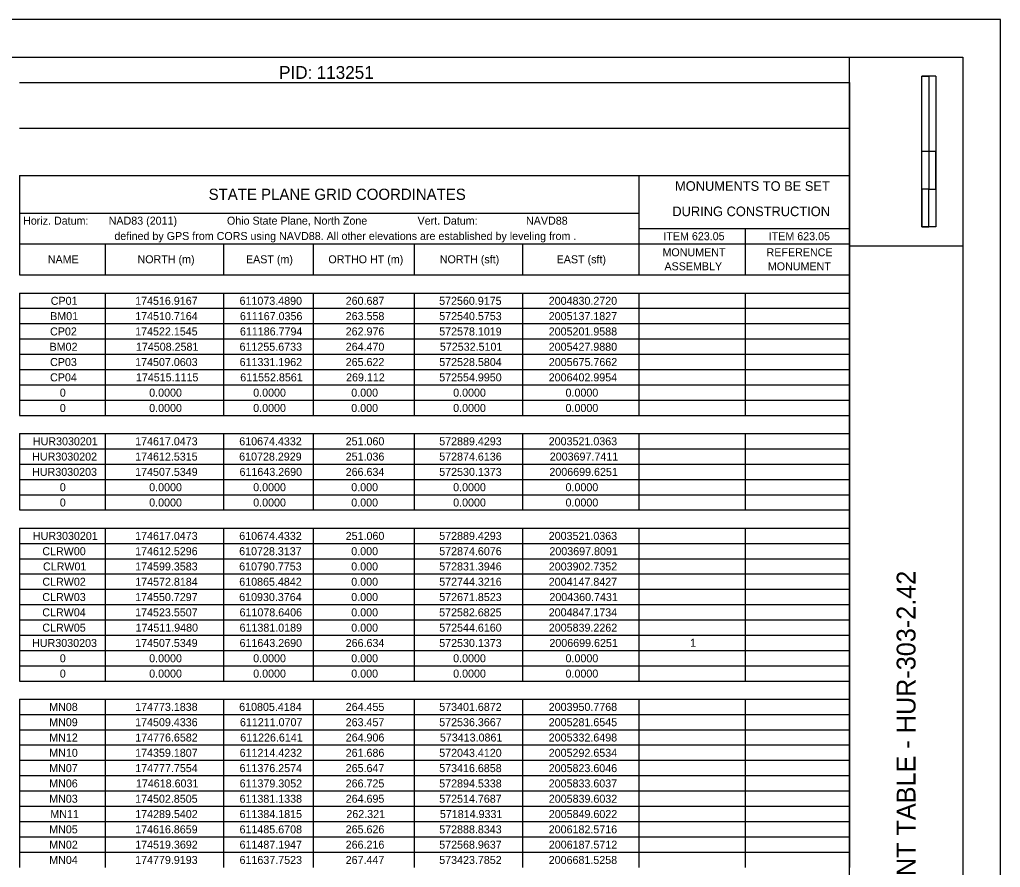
# Model space of a CAD drawing. Extents: x 0 to 34, y 0 to 22.
# Drawn here: x 21 to 34, y 10.76 to 22 of the extents above; entities that cross this region are included whole.
import ezdxf

# ---------------------------------------------------------------- set-up
doc = ezdxf.new("R2010")
doc.units = 0
for name, color, linetype in [('SH_Border', 7, 'Continuous'), ('SH_Cut_Line', 7, 'Continuous'), ('SH_Data', 7, 'Continuous'), ('SH_Text', 7, 'Continuous')]:
    doc.layers.add(name, color=color, linetype=linetype)

msp = doc.modelspace()

# ---------------------------------------------------------------- linework, layer by layer
at = {"layer": 'SH_Border'}
for p, q in [((32, 0.5), (32, 21.5)), ((32, 19), (33.5, 19))]:
    msp.add_line(p, q, dxfattribs=at)
msp.add_lwpolyline([(1.5, 21.5), (33.5, 21.5), (33.5, 0.5), (1.5, 0.5)], close=True, dxfattribs=at)
at = {"layer": 'SH_Cut_Line'}
msp.add_lwpolyline([(0, 0), (34, 0), (34, 22), (0, 22)], close=True, dxfattribs=at)
at = {"layer": 'SH_Data'}
for p, q in [((32.957, 19.25), (32.957, 21.25)), ((33.144, 21.25), (32.957, 21.25)), ((32.957, 20.25), (32.957, 21.25)), ((32.957, 21.25), (33.05, 21.25)), ((33.05, 21.25), (33.051, 21.25)), ((33.051, 21.25), (33.051, 20.25)), ((33.144, 21.25), (33.144, 19.25)), ((33.051, 20.25), (32.957, 20.25)), ((33.143, 20.25), (33.05, 20.25)), ((33.05, 20.25), (33.05, 19.75)), ((33.143, 19.75), (33.143, 20.25)), ((33.05, 19.75), (32.957, 19.75)), ((32.957, 19.75), (32.957, 19.25)), ((33.05, 19.75), (33.143, 19.75)), ((33.05, 19.25), (33.05, 19.75)), ((33.144, 19.25), (32.957, 19.25)), ((32.957, 19.25), (33.05, 19.25))]:
    msp.add_line(p, q, dxfattribs=at)
at = {"layer": 'SH_Text'}
for p, q in [((20.997, 21.168), (22.132, 21.168)), ((22.132, 21.168), (32, 21.168)), ((32, 21.168), (32, 19.932)), ((20.997, 20.559), (22.132, 20.559)), ((22.132, 20.559), (32, 20.559)), ((20.997, 19.932), (22.132, 19.932)), ((20.997, 19.932), (20.997, 19.028)), ((22.132, 19.932), (32, 19.932)), ((29.205, 19.932), (29.205, 19.028)), ((32, 19.932), (32, 19.028)), ((20.997, 19.434), (22.132, 19.434)), ((22.132, 19.434), (29.205, 19.434)), ((29.205, 19.231), (32, 19.231)), ((30.617, 19.231), (30.617, 19.028)), ((20.997, 19.028), (22.132, 19.028)), ((20.997, 19.028), (20.997, 18.613)), ((22.132, 19.028), (32, 19.028)), ((22.132, 19.028), (22.132, 18.613)), ((23.699, 19.028), (23.699, 18.613)), ((24.889, 19.028), (24.889, 18.613)), ((26.226, 19.028), (26.226, 18.613)), ((27.665, 19.028), (27.665, 18.613)), ((29.205, 19.028), (29.205, 18.613)), ((30.617, 19.028), (30.617, 18.613)), ((32, 19.028), (32, 17.359)), ((20.997, 18.613), (22.132, 18.613)), ((22.132, 18.613), (32, 18.613)), ((20.997, 18.373), (22.132, 18.373)), ((20.997, 18.373), (20.997, 17.359)), ((22.132, 18.373), (32, 18.373)), ((22.132, 18.373), (22.132, 17.359)), ((23.699, 18.373), (23.699, 17.359)), ((24.889, 18.373), (24.889, 17.359)), ((26.226, 18.373), (26.226, 17.359)), ((27.665, 18.373), (27.665, 17.359)), ((29.205, 18.373), (29.205, 17.359)), ((30.617, 18.373), (30.617, 17.359)), ((20.997, 18.171), (22.132, 18.171)), ((22.132, 18.171), (32, 18.171)), ((20.997, 17.968), (22.132, 17.968)), ((22.132, 17.968), (32, 17.968)), ((20.997, 17.765), (22.132, 17.765)), ((22.132, 17.765), (32, 17.765)), ((20.997, 17.562), (22.132, 17.562)), ((22.132, 17.562), (32, 17.562)), ((20.997, 17.359), (22.132, 17.359)), ((20.997, 17.359), (20.997, 17.156)), ((22.132, 17.359), (32, 17.359)), ((22.132, 17.359), (22.132, 17.156)), ((23.699, 17.359), (23.699, 17.156)), ((24.889, 17.359), (24.889, 17.156)), ((26.226, 17.359), (26.226, 17.156)), ((27.665, 17.359), (27.665, 17.156)), ((29.205, 17.359), (29.205, 17.156)), ((30.617, 17.359), (30.617, 17.156)), ((32, 17.359), (32, 17.156)), ((20.997, 17.156), (22.132, 17.156)), ((20.997, 17.156), (20.997, 16.953)), ((22.132, 17.156), (32, 17.156)), ((22.132, 17.156), (22.132, 16.953)), ((23.699, 17.156), (23.699, 16.953)), ((24.889, 17.156), (24.889, 16.953)), ((26.226, 17.156), (26.226, 16.953)), ((27.665, 17.156), (27.665, 16.953)), ((29.205, 17.156), (29.205, 16.953)), ((30.617, 17.156), (30.617, 16.953)), ((32, 17.156), (32, 16.953)), ((20.997, 16.953), (22.132, 16.953)), ((20.997, 16.953), (20.997, 16.75)), ((22.132, 16.953), (32, 16.953)), ((22.132, 16.953), (22.132, 16.75)), ((23.699, 16.953), (23.699, 16.75)), ((24.889, 16.953), (24.889, 16.75)), ((26.226, 16.953), (26.226, 16.75)), ((27.665, 16.953), (27.665, 16.75)), ((29.205, 16.953), (29.205, 16.75)), ((30.617, 16.953), (30.617, 16.75)), ((32, 16.953), (32, 16.51)), ((20.997, 16.75), (22.132, 16.75)), ((22.132, 16.75), (32, 16.75)), ((20.997, 16.51), (22.132, 16.51)), ((20.997, 16.51), (20.997, 16.308)), ((22.132, 16.51), (32, 16.51)), ((22.132, 16.51), (22.132, 16.308)), ((23.699, 16.51), (23.699, 16.308)), ((24.889, 16.51), (24.889, 16.308)), ((26.226, 16.51), (26.226, 16.308)), ((27.665, 16.51), (27.665, 16.308)), ((29.205, 16.51), (29.205, 16.308)), ((30.617, 16.51), (30.617, 16.308)), ((32, 16.51), (32, 16.308)), ((20.997, 16.308), (22.132, 16.308)), ((20.997, 16.308), (20.997, 15.496)), ((22.132, 16.308), (32, 16.308)), ((22.132, 16.308), (22.132, 15.496)), ((23.699, 16.308), (23.699, 15.496)), ((24.889, 16.308), (24.889, 15.496)), ((26.226, 16.308), (26.226, 15.496)), ((27.665, 16.308), (27.665, 15.496)), ((29.205, 16.308), (29.205, 15.496)), ((30.617, 16.308), (30.617, 15.496)), ((32, 16.308), (32, 13.227)), ((20.997, 16.105), (22.132, 16.105)), ((22.132, 16.105), (32, 16.105)), ((20.997, 15.902), (22.132, 15.902)), ((22.132, 15.902), (32, 15.902)), ((20.997, 15.699), (22.132, 15.699)), ((22.132, 15.699), (32, 15.699)), ((20.997, 15.496), (22.132, 15.496)), ((22.132, 15.496), (32, 15.496)), ((20.997, 15.256), (22.132, 15.256)), ((20.997, 15.256), (20.997, 13.227)), ((22.132, 15.256), (32, 15.256)), ((22.132, 15.256), (22.132, 13.227)), ((23.699, 15.256), (23.699, 13.227)), ((24.889, 15.256), (24.889, 13.227)), ((26.226, 15.256), (26.226, 13.227)), ((27.665, 15.256), (27.665, 13.227)), ((29.205, 15.256), (29.205, 13.227)), ((30.617, 15.256), (30.617, 13.227)), ((20.997, 15.053), (22.132, 15.053)), ((22.132, 15.053), (32, 15.053)), ((20.997, 14.85), (22.132, 14.85)), ((22.132, 14.85), (32, 14.85)), ((20.997, 14.647), (22.132, 14.647)), ((22.132, 14.647), (32, 14.647)), ((20.997, 14.445), (22.132, 14.445)), ((22.132, 14.445), (32, 14.445)), ((20.997, 14.242), (22.132, 14.242)), ((22.132, 14.242), (32, 14.242)), ((20.997, 14.039), (22.132, 14.039)), ((22.132, 14.039), (32, 14.039)), ((20.997, 13.836), (22.132, 13.836)), ((22.132, 13.836), (32, 13.836)), ((20.997, 13.633), (22.132, 13.633)), ((22.132, 13.633), (32, 13.633)), ((20.997, 13.43), (22.132, 13.43)), ((22.132, 13.43), (32, 13.43)), ((20.997, 13.227), (22.132, 13.227)), ((22.132, 13.227), (32, 13.227)), ((32, 13.227), (32, 12.987)), ((20.997, 12.987), (22.132, 12.987)), ((20.997, 12.987), (20.997, 12.784)), ((22.132, 12.987), (32, 12.987)), ((22.132, 12.987), (22.132, 12.784)), ((23.699, 12.987), (23.699, 12.784)), ((24.889, 12.987), (24.889, 12.784)), ((26.226, 12.987), (26.226, 12.784)), ((27.665, 12.987), (27.665, 12.784)), ((29.205, 12.987), (29.205, 12.784)), ((30.617, 12.987), (30.617, 12.784)), ((32, 12.987), (32, 12.784)), ((20.997, 12.784), (22.132, 12.784)), ((20.997, 12.784), (20.997, 12.581)), ((22.132, 12.784), (32, 12.784)), ((22.132, 12.784), (22.132, 12.581)), ((23.699, 12.784), (23.699, 12.581)), ((24.889, 12.784), (24.889, 12.581)), ((26.226, 12.784), (26.226, 12.581)), ((27.665, 12.784), (27.665, 12.581)), ((29.205, 12.784), (29.205, 12.581)), ((30.617, 12.784), (30.617, 12.581)), ((32, 12.784), (32, 12.581)), ((20.997, 12.581), (22.132, 12.581)), ((20.997, 12.581), (20.997, 12.379)), ((22.132, 12.581), (32, 12.581)), ((22.132, 12.581), (22.132, 12.379)), ((23.699, 12.581), (23.699, 12.379)), ((24.889, 12.581), (24.889, 12.379)), ((26.226, 12.581), (26.226, 12.379)), ((27.665, 12.581), (27.665, 12.379)), ((29.205, 12.581), (29.205, 12.379)), ((30.617, 12.581), (30.617, 12.379)), ((32, 12.581), (32, 12.379)), ((20.997, 12.379), (22.132, 12.379)), ((20.997, 12.379), (20.997, 11.973)), ((22.132, 12.379), (32, 12.379)), ((22.132, 12.379), (22.132, 11.973)), ((23.699, 12.379), (23.699, 11.973)), ((24.889, 12.379), (24.889, 11.973)), ((26.226, 12.379), (26.226, 11.973)), ((27.665, 12.379), (27.665, 11.973)), ((29.205, 12.379), (29.205, 11.973)), ((30.617, 12.379), (30.617, 11.973)), ((32, 12.379), (32, 11.973)), ((20.997, 12.176), (22.132, 12.176)), ((22.132, 12.176), (32, 12.176)), ((20.997, 11.973), (22.132, 11.973)), ((20.997, 11.973), (20.997, 11.77)), ((22.132, 11.973), (32, 11.973)), ((22.132, 11.973), (22.132, 11.77)), ((23.699, 11.973), (23.699, 11.77)), ((24.889, 11.973), (24.889, 11.77)), ((26.226, 11.973), (26.226, 11.77)), ((27.665, 11.973), (27.665, 11.77)), ((29.205, 11.973), (29.205, 11.77)), ((30.617, 11.973), (30.617, 11.77)), ((32, 11.973), (32, 11.77)), ((20.997, 11.77), (22.132, 11.77)), ((20.997, 11.77), (20.997, 11.567)), ((22.132, 11.77), (32, 11.77)), ((22.132, 11.77), (22.132, 11.567)), ((23.699, 11.77), (23.699, 11.567)), ((24.889, 11.77), (24.889, 11.567)), ((26.226, 11.77), (26.226, 11.567)), ((27.665, 11.77), (27.665, 11.567)), ((29.205, 11.77), (29.205, 11.567)), ((30.617, 11.77), (30.617, 11.567)), ((32, 11.77), (32, 11.567)), ((20.997, 11.567), (22.132, 11.567)), ((20.997, 11.567), (20.997, 11.364)), ((22.132, 11.567), (32, 11.567)), ((22.132, 11.567), (22.132, 11.364)), ((23.699, 11.567), (23.699, 11.364)), ((24.889, 11.567), (24.889, 11.364)), ((26.226, 11.567), (26.226, 11.364)), ((27.665, 11.567), (27.665, 11.364)), ((29.205, 11.567), (29.205, 11.364)), ((30.617, 11.567), (30.617, 11.364)), ((32, 11.567), (32, 11.364)), ((20.997, 11.364), (22.132, 11.364)), ((20.997, 11.364), (20.997, 10.958)), ((22.132, 11.364), (32, 11.364)), ((22.132, 11.364), (22.132, 10.958)), ((23.699, 11.364), (23.699, 10.958)), ((24.889, 11.364), (24.889, 10.958)), ((26.226, 11.364), (26.226, 10.958)), ((27.665, 11.364), (27.665, 10.958)), ((29.205, 11.364), (29.205, 10.958)), ((30.617, 11.364), (30.617, 10.958)), ((32, 11.364), (32, 10.958)), ((20.997, 11.161), (22.132, 11.161)), ((22.132, 11.161), (32, 11.161)), ((20.997, 10.958), (22.132, 10.958)), ((20.997, 10.958), (20.997, 10.755)), ((22.132, 10.958), (32, 10.958)), ((22.132, 10.958), (22.132, 10.755)), ((23.699, 10.958), (23.699, 10.755)), ((24.889, 10.958), (24.889, 10.755)), ((26.226, 10.958), (26.226, 10.755)), ((27.665, 10.958), (27.665, 10.755)), ((29.205, 10.958), (29.205, 10.755)), ((30.617, 10.958), (30.617, 10.755)), ((32, 10.958), (32, 10.755))]:
    msp.add_line(p, q, dxfattribs=at)

# ---------------------------------------------------------------- texts
at = {"layer": 'SH_Data'}
msp.add_text('MONUMENT TABLE - HUR-303-2.42', height=0.25, rotation=90, dxfattribs=at).set_placement((32.875, 9.117))
at = {"layer": 'SH_Text'}
for s, height, p in [('PID:', 0.1697, (24.437, 21.214)), ('113251', 0.1697, (24.935, 21.214)), ('  MONUMENTS TO BE SET', 0.12728, (29.592, 19.729)), ('STATE PLANE GRID COORDINATES', 0.14849, (23.503, 19.609)), (' DURING CONSTRUCTION', 0.12728, (29.604, 19.393)), ('Horiz. Datum:', 0.10606, (21.043, 19.28)), ('NAD83 (2011)', 0.10606, (22.178, 19.28)), ('Ohio State Plane, North Zone', 0.10606, (23.746, 19.28)), ('Vert. Datum:', 0.10606, (26.273, 19.28)), ('NAVD88', 0.1061, (27.711, 19.28)), (' defined by GPS from CORS using NAVD88. All other elevations are established by leveling from .', 0.10606, (22.214, 19.077)), ('ITEM 623.05', 0.10606, (29.532, 19.074)), ('ITEM 623.05', 0.10606, (30.929, 19.074)), ('NAME', 0.1061, (21.371, 18.768)), ('NORTH (m)', 0.1061, (22.56, 18.768)), ('EAST (m)', 0.1061, (23.998, 18.768)), ('ORTHO HT (m)', 0.10606, (25.091, 18.768)), ('NORTH (sft)', 0.10606, (26.568, 18.768)), ('EAST (sft)', 0.1061, (28.117, 18.768)), ('MONUMENT ', 0.1061, (29.52, 18.861)), ('REFERENCE ', 0.1061, (30.9, 18.861)), ('ASSEMBLY', 0.1061, (29.546, 18.675)), ('MONUMENT', 0.1061, (30.917, 18.675)), ('CP01', 0.1061, (21.41, 18.217)), ('174516.9167', 0.10606, (22.529, 18.217)), ('611073.4890', 0.10606, (23.913, 18.217)), ('260.687', 0.1061, (25.32, 18.217)), ('572560.9175', 0.10606, (26.559, 18.217)), ('2004830.2720', 0.10606, (28.012, 18.217)), ('BM01', 0.1061, (21.402, 18.014)), ('174510.7164', 0.10606, (22.53, 18.014)), ('611167.0356', 0.10606, (23.918, 18.014)), ('263.558', 0.1061, (25.32, 18.014)), ('572540.5753', 0.10606, (26.56, 18.014)), ('2005137.1827', 0.10606, (28.012, 18.014)), ('CP02', 0.1061, (21.401, 17.811)), ('174522.1545', 0.10606, (22.529, 17.811)), ('611186.7794', 0.10606, (23.918, 17.811)), ('262.976', 0.1061, (25.32, 17.811)), ('572578.1019', 0.10606, (26.56, 17.811)), ('2005201.9588', 0.10606, (28.012, 17.811)), ('BM02', 0.1061, (21.394, 17.608)), ('174508.2581', 0.10606, (22.539, 17.608)), ('611255.6733', 0.10606, (23.913, 17.608)), ('264.470', 0.1061, (25.32, 17.608)), ('572532.5101', 0.10606, (26.569, 17.608)), ('2005427.9880', 0.10606, (28.012, 17.608)), ('CP03', 0.1061, (21.401, 17.405)), ('174507.0603', 0.10606, (22.529, 17.405)), ('611331.1962', 0.10606, (23.914, 17.405)), ('265.622', 0.1061, (25.32, 17.405)), ('572528.5804', 0.10606, (26.56, 17.405)), ('2005675.7662', 0.10606, (28.013, 17.405)), ('CP04', 0.1061, (21.401, 17.202)), ('174515.1115', 0.10606, (22.539, 17.202)), ('611552.8561', 0.10606, (23.922, 17.202)), ('269.112', 0.1061, (25.325, 17.202)), ('572554.9950', 0.10606, (26.56, 17.202)), ('2006402.9954', 0.10606, (28.012, 17.202)), ('0', 0.106, (21.53, 16.999)), ('0.0000', 0.1061, (22.715, 16.999)), ('0.0000', 0.1061, (24.094, 16.999)), ('0.000', 0.1061, (25.394, 16.999)), ('0.0000', 0.1061, (26.745, 16.999)), ('0.0000', 0.1061, (28.235, 16.999)), ('0', 0.106, (21.53, 16.796)), ('0.0000', 0.1061, (22.715, 16.796)), ('0.0000', 0.1061, (24.094, 16.796)), ('0.000', 0.1061, (25.394, 16.796)), ('0.0000', 0.1061, (26.745, 16.796)), ('0.0000', 0.1061, (28.235, 16.796)), ('HUR3030201', 0.1061, (21.173, 16.354)), ('174617.0473', 0.10606, (22.529, 16.354)), ('610674.4332', 0.10606, (23.909, 16.354)), ('251.060', 0.1061, (25.32, 16.354)), ('572889.4293', 0.10606, (26.56, 16.354)), ('2003521.0363', 0.10606, (28.012, 16.354)), ('HUR3030202', 0.1061, (21.164, 16.151)), ('174612.5315', 0.10606, (22.529, 16.151)), ('610728.2929', 0.10606, (23.908, 16.151)), ('251.036', 0.1061, (25.32, 16.151)), ('572874.6136', 0.10606, (26.56, 16.151)), ('2003697.7411', 0.10606, (28.026, 16.151)), ('HUR3030203', 0.1061, (21.163, 15.948)), ('174507.5349', 0.10606, (22.529, 15.948)), ('611643.2690', 0.10606, (23.913, 15.948)), ('266.634', 0.1061, (25.32, 15.948)), ('572530.1373', 0.10606, (26.56, 15.948)), ('2006699.6251', 0.10606, (28.021, 15.948)), ('0', 0.106, (21.53, 15.745)), ('0.0000', 0.1061, (22.715, 15.745)), ('0.0000', 0.1061, (24.094, 15.745)), ('0.000', 0.1061, (25.394, 15.745)), ('0.0000', 0.1061, (26.745, 15.745)), ('0.0000', 0.1061, (28.235, 15.745)), ('0', 0.106, (21.53, 15.542)), ('0.0000', 0.1061, (22.715, 15.542)), ('0.0000', 0.1061, (24.094, 15.542)), ('0.000', 0.1061, (25.394, 15.542)), ('0.0000', 0.1061, (26.745, 15.542)), ('0.0000', 0.1061, (28.235, 15.542)), ('HUR3030201', 0.1061, (21.173, 15.099)), ('174617.0473', 0.10606, (22.529, 15.099)), ('610674.4332', 0.10606, (23.909, 15.099)), ('251.060', 0.1061, (25.32, 15.099)), ('572889.4293', 0.10606, (26.56, 15.099)), ('2003521.0363', 0.10606, (28.012, 15.099)), ('CLRW00', 0.1061, (21.298, 14.896)), ('174612.5296', 0.10606, (22.529, 14.896)), ('610728.3137', 0.10606, (23.908, 14.896)), ('0.000', 0.1061, (25.394, 14.896)), ('572874.6076', 0.10606, (26.56, 14.896)), ('2003697.8091', 0.10606, (28.021, 14.896)), ('CLRW01', 0.1061, (21.307, 14.694)), ('174599.3583', 0.10606, (22.529, 14.694)), ('610790.7753', 0.10606, (23.908, 14.694)), ('0.000', 0.1061, (25.394, 14.694)), ('572831.3946', 0.10606, (26.56, 14.694)), ('2003902.7352', 0.10606, (28.013, 14.694)), ('CLRW02', 0.1061, (21.299, 14.491)), ('174572.8184', 0.10606, (22.53, 14.491)), ('610865.4842', 0.10606, (23.909, 14.491)), ('0.000', 0.1061, (25.394, 14.491)), ('572744.3216', 0.10606, (26.56, 14.491)), ('2004147.8427', 0.10606, (28.012, 14.491)), ('CLRW03', 0.1061, (21.298, 14.288)), ('174550.7297', 0.10606, (22.529, 14.288)), ('610930.3764', 0.10606, (23.908, 14.288)), ('0.000', 0.1061, (25.394, 14.288)), ('572671.8523', 0.10606, (26.56, 14.288)), ('2004360.7431', 0.10606, (28.021, 14.288)), ('CLRW04', 0.1061, (21.298, 14.085)), ('174523.5507', 0.10606, (22.529, 14.085)), ('611078.6406', 0.10606, (23.913, 14.085)), ('0.000', 0.1061, (25.394, 14.085)), ('572582.6825', 0.10606, (26.559, 14.085)), ('2004847.1734', 0.10606, (28.012, 14.085)), ('CLRW05', 0.1061, (21.298, 13.882)), ('174511.9480', 0.10606, (22.534, 13.882)), ('611381.0189', 0.10606, (23.913, 13.882)), ('0.000', 0.1061, (25.394, 13.882)), ('572544.6160', 0.10606, (26.56, 13.882)), ('2005839.2262', 0.10606, (28.013, 13.882)), ('HUR3030203', 0.1061, (21.163, 13.679)), ('174507.5349', 0.10606, (22.529, 13.679)), ('611643.2690', 0.10606, (23.913, 13.679)), ('266.634', 0.1061, (25.32, 13.679)), ('572530.1373', 0.10606, (26.56, 13.679)), ('2006699.6251', 0.10606, (28.021, 13.679)), ('1', 0.106, (29.886, 13.681)), ('0', 0.106, (21.53, 13.476)), ('0.0000', 0.1061, (22.715, 13.476)), ('0.0000', 0.1061, (24.094, 13.476)), ('0.000', 0.1061, (25.394, 13.476)), ('0.0000', 0.1061, (26.745, 13.476)), ('0.0000', 0.1061, (28.235, 13.476)), ('0', 0.106, (21.53, 13.273)), ('0.0000', 0.1061, (22.715, 13.273)), ('0.0000', 0.1061, (24.094, 13.273)), ('0.000', 0.1061, (25.394, 13.273)), ('0.0000', 0.1061, (26.745, 13.273)), ('0.0000', 0.1061, (28.235, 13.273)), ('MN08', 0.1061, (21.389, 12.831)), ('174773.1838', 0.10606, (22.529, 12.831)), ('610805.4184', 0.10606, (23.908, 12.831)), ('264.455', 0.1061, (25.32, 12.831)), ('573401.6872', 0.10606, (26.56, 12.831)), ('2003950.7768', 0.10606, (28.012, 12.831)), ('MN09', 0.1061, (21.389, 12.628)), ('174509.4336', 0.10606, (22.529, 12.628)), ('611211.0707', 0.10606, (23.918, 12.628)), ('263.457', 0.1061, (25.32, 12.628)), ('572536.3667', 0.10606, (26.56, 12.628)), ('2005281.6545', 0.10606, (28.012, 12.628)), ('MN12', 0.1061, (21.39, 12.425)), ('174776.6582', 0.10606, (22.53, 12.425)), ('611226.6141', 0.10606, (23.922, 12.425)), ('264.906', 0.1061, (25.32, 12.425)), ('573413.0861', 0.10606, (26.569, 12.425)), ('2005332.6498', 0.10606, (28.012, 12.425)), ('MN10', 0.1061, (21.39, 12.222)), ('174359.1807', 0.10606, (22.529, 12.222)), ('611214.4232', 0.10606, (23.914, 12.222)), ('261.686', 0.1061, (25.32, 12.222)), ('572043.4120', 0.10606, (26.56, 12.222)), ('2005292.6534', 0.10606, (28.012, 12.222)), ('MN07', 0.1061, (21.389, 12.019)), ('174777.7554', 0.10606, (22.53, 12.019)), ('611376.2574', 0.10606, (23.913, 12.019)), ('265.647', 0.1061, (25.32, 12.019)), ('573416.6858', 0.10606, (26.56, 12.019)), ('2005823.6046', 0.10606, (28.012, 12.019)), ('MN06', 0.1061, (21.389, 11.816)), ('174618.6031', 0.10606, (22.539, 11.816)), ('611379.3052', 0.10606, (23.914, 11.816)), ('266.725', 0.1061, (25.32, 11.816)), ('572894.5338', 0.10606, (26.56, 11.816)), ('2005833.6037', 0.10606, (28.012, 11.816)), ('MN03', 0.1061, (21.389, 11.613)), ('174502.8505', 0.10606, (22.529, 11.613)), ('611381.1338', 0.10606, (23.913, 11.613)), ('264.695', 0.1061, (25.32, 11.613)), ('572514.7687', 0.10606, (26.56, 11.613)), ('2005839.6032', 0.10606, (28.013, 11.613)), ('MN11', 0.1061, (21.404, 11.41)), ('174289.5402', 0.10606, (22.53, 11.41)), ('611384.1815', 0.10606, (23.913, 11.41)), ('262.321', 0.1061, (25.329, 11.41)), ('571814.9331', 0.10606, (26.569, 11.41)), ('2005849.6022', 0.10606, (28.013, 11.41)), ('MN05', 0.1061, (21.389, 11.207)), ('174616.8659', 0.10606, (22.529, 11.207)), ('611485.6708', 0.10606, (23.913, 11.207)), ('265.626', 0.1061, (25.32, 11.207)), ('572888.8343', 0.10606, (26.56, 11.207)), ('2006182.5716', 0.10606, (28.012, 11.207)), ('MN02', 0.1061, (21.39, 11.004)), ('174519.3692', 0.10606, (22.53, 11.004)), ('611487.1947', 0.10606, (23.913, 11.004)), ('266.216', 0.1061, (25.32, 11.004)), ('572568.9637', 0.10606, (26.56, 11.004)), ('2006187.5712', 0.10606, (28.013, 11.004)), ('MN04', 0.1061, (21.39, 10.801)), ('174779.9193', 0.10606, (22.529, 10.801)), ('611637.7523', 0.10606, (23.913, 10.801)), ('267.447', 0.1061, (25.32, 10.801)), ('573423.7852', 0.10606, (26.56, 10.801)), ('2006681.5258', 0.10606, (28.012, 10.801))]:
    msp.add_text(s, height=height, dxfattribs=at).set_placement(p)

doc.saveas('drawing.dxf')
